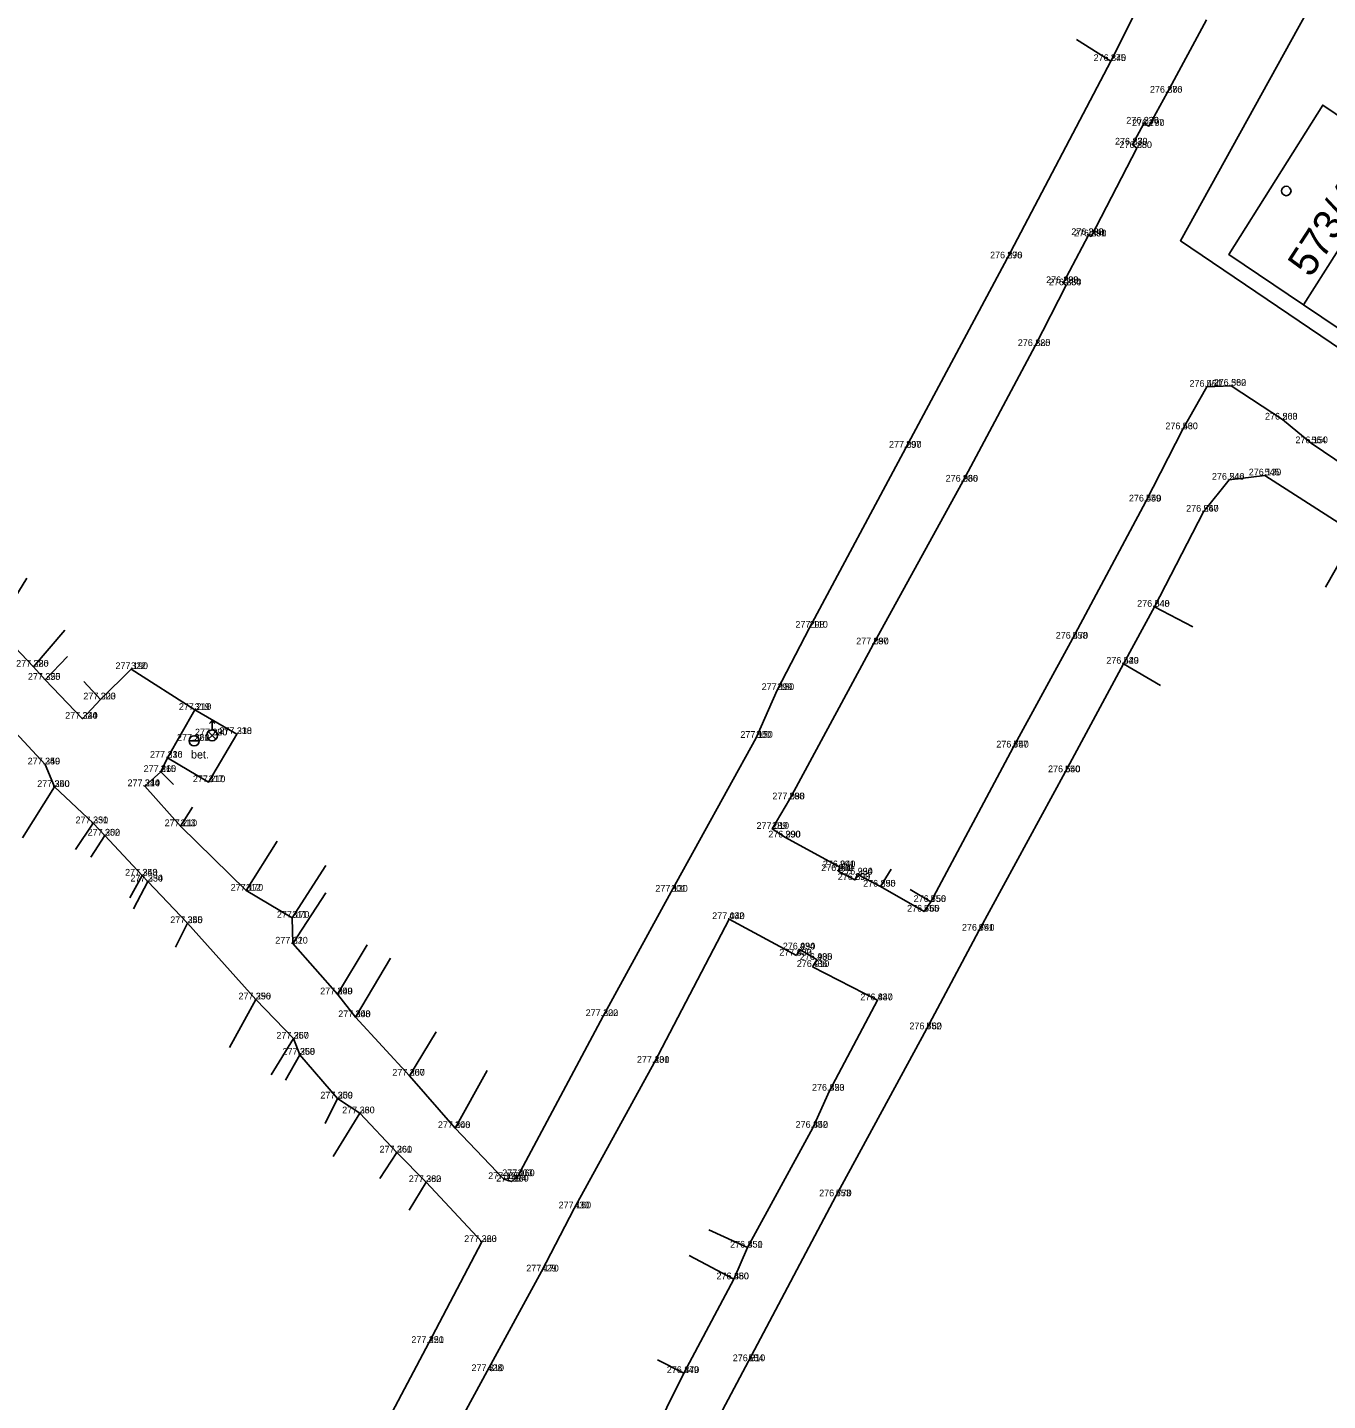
# Model space of a CAD drawing. Extents: x -776701 to -776081, y -974398 to -973771.
# Drawn here: x -776485.8 to -776437.5, y -974052.6 to -974001.5 of the extents above; entities that cross this region are included whole.
import ezdxf

# ---------------------------------------------------------------- set-up
doc = ezdxf.new("R2010")
doc.units = 0
for name, color, linetype in [('1 Body-bod', 7, 'Continuous'), ('10 Silnice-chodniky', 7, 'Continuous'), ('11 Rozhrani-nezpev zpev schody', 7, 'Continuous'), ('2 Body-cislo', 7, 'Continuous'), ('3 Body-vyska', 7, 'Continuous'), ('35 Studna', 7, 'Continuous'), ('40 Popis-povrch', 7, 'Continuous'), ('58 Mobiliar', 7, 'Continuous'), ('7 Ploty', 7, 'Continuous'), ('Hranice parcel', 7, 'Continuous'), ('Parcelní čísla', 7, 'Continuous'), ('Značky budov', 7, 'Continuous')]:
    doc.layers.add(name, color=color, linetype=linetype)

msp = doc.modelspace()

# ---------------------------------------------------------------- linework, layer by layer
at = {"layer": '1 Body-bod'}
for p, q in [((-776445.52, -974002.73), (-776445.52, -974002.73)), ((-776443.42, -974003.91), (-776443.42, -974003.91)), ((-776444.29, -974005.06), (-776444.29, -974005.06)), ((-776444.1, -974005.15), (-776444.1, -974005.15)), ((-776444.71, -974005.84), (-776444.71, -974005.84)), ((-776444.55, -974005.97), (-776444.55, -974005.97)), ((-776446.35, -974009.21), (-776446.35, -974009.21)), ((-776446.25, -974009.26), (-776446.25, -974009.26)), ((-776449.38, -974010.08), (-776449.38, -974010.08)), ((-776447.29, -974011), (-776447.29, -974011)), ((-776447.18, -974011.08), (-776447.18, -974011.08)), ((-776448.33, -974013.34), (-776448.33, -974013.34)), ((-776441.95, -974014.86), (-776441.95, -974014.86)), ((-776441.04, -974014.82), (-776441.04, -974014.82)), ((-776439.13, -974016.08), (-776439.13, -974016.08)), ((-776442.84, -974016.44), (-776442.84, -974016.44)), ((-776453.14, -974017.13), (-776453.14, -974017.13)), ((-776438.06, -974016.96), (-776438.06, -974016.96)), ((-776441.11, -974018.32), (-776441.11, -974018.32)), ((-776439.79, -974018.16), (-776439.79, -974018.16)), ((-776451.03, -974018.39), (-776451.03, -974018.39)), ((-776444.21, -974019.13), (-776444.21, -974019.13)), ((-776442.07, -974019.51), (-776442.07, -974019.51)), ((-776443.89, -974023.05), (-776443.89, -974023.05)), ((-776456.73, -974023.83), (-776456.73, -974023.83)), ((-776454.36, -974024.45), (-776454.36, -974024.45)), ((-776446.94, -974024.24), (-776446.94, -974024.24)), ((-776485.61, -974025.28), (-776485.61, -974025.28)), ((-776481.98, -974025.37), (-776481.98, -974025.37)), ((-776445.04, -974025.17), (-776445.04, -974025.17)), ((-776485.17, -974025.77), (-776485.17, -974025.77)), ((-776483.11, -974026.5), (-776483.11, -974026.5)), ((-776457.93, -974026.15), (-776457.93, -974026.15)), ((-776479.61, -974026.89), (-776479.61, -974026.89)), ((-776483.79, -974027.22), (-776483.79, -974027.22)), ((-776479.63, -974028.04), (-776479.63, -974028.04)), ((-776478.96, -974027.84), (-776478.96, -974027.84)), ((-776478.04, -974027.79), (-776478.04, -974027.79)), ((-776458.72, -974027.93), (-776458.72, -974027.93)), ((-776449.15, -974028.29), (-776449.15, -974028.29)), ((-776485.18, -974028.92), (-776485.18, -974028.92)), ((-776480.62, -974028.67), (-776480.62, -974028.67)), ((-776480.87, -974029.2), (-776480.87, -974029.2)), ((-776479.09, -974029.58), (-776479.09, -974029.58)), ((-776447.22, -974029.21), (-776447.22, -974029.21)), ((-776484.83, -974029.76), (-776484.83, -974029.76)), ((-776481.47, -974029.73), (-776481.47, -974029.73)), ((-776457.48, -974030.22), (-776457.48, -974030.22)), ((-776483.39, -974031.11), (-776483.39, -974031.11)), ((-776482.95, -974031.57), (-776482.95, -974031.57)), ((-776480.14, -974031.22), (-776480.14, -974031.22)), ((-776458.12, -974031.32), (-776458.12, -974031.32)), ((-776457.63, -974031.64), (-776457.63, -974031.64)), ((-776481.56, -974033.06), (-776481.56, -974033.06)), ((-776455.66, -974032.89), (-776455.66, -974032.89)), ((-776455.6, -974032.75), (-776455.6, -974032.75)), ((-776454.94, -974033.02), (-776454.94, -974033.02)), ((-776481.35, -974033.28), (-776481.35, -974033.28)), ((-776477.7, -974033.62), (-776477.7, -974033.62)), ((-776461.88, -974033.66), (-776461.88, -974033.66)), ((-776455.04, -974033.22), (-776455.04, -974033.22)), ((-776454.09, -974033.47), (-776454.09, -974033.47)), ((-776452.22, -974034.04), (-776452.22, -974034.04)), ((-776475.98, -974034.63), (-776475.98, -974034.63)), ((-776459.72, -974034.68), (-776459.72, -974034.68)), ((-776452.47, -974034.4), (-776452.47, -974034.4)), ((-776479.88, -974034.83), (-776479.88, -974034.83)), ((-776450.43, -974035.11), (-776450.43, -974035.11)), ((-776475.96, -974035.59), (-776475.96, -974035.59)), ((-776457.21, -974036.04), (-776457.21, -974036.04)), ((-776457.09, -974035.81), (-776457.09, -974035.81)), ((-776456.45, -974036.2), (-776456.45, -974036.2)), ((-776456.62, -974036.46), (-776456.62, -974036.46)), ((-776477.34, -974037.67), (-776477.34, -974037.67)), ((-776474.3, -974037.48), (-776474.3, -974037.48)), ((-776454.2, -974037.7), (-776454.2, -974037.7)), ((-776473.63, -974038.33), (-776473.63, -974038.33)), ((-776464.41, -974038.29), (-776464.41, -974038.29)), ((-776452.38, -974038.78), (-776452.38, -974038.78)), ((-776475.93, -974039.13), (-776475.93, -974039.13)), ((-776475.7, -974039.73), (-776475.7, -974039.73)), ((-776462.51, -974040.03), (-776462.51, -974040.03)), ((-776471.61, -974040.51), (-776471.61, -974040.51)), ((-776455.99, -974041.07), (-776455.99, -974041.07)), ((-776474.29, -974041.36), (-776474.29, -974041.36)), ((-776473.47, -974041.91), (-776473.47, -974041.91)), ((-776469.92, -974042.46), (-776469.92, -974042.46)), ((-776456.61, -974042.45), (-776456.61, -974042.45)), ((-776472.09, -974043.37), (-776472.09, -974043.37)), ((-776468.11, -974044.36), (-776468.11, -974044.36)), ((-776467.59, -974044.25), (-776467.59, -974044.25)), ((-776471, -974044.47), (-776471, -974044.47)), ((-776467.81, -974044.45), (-776467.81, -974044.45)), ((-776455.75, -974045), (-776455.75, -974045)), ((-776465.49, -974045.45), (-776465.49, -974045.45)), ((-776468.93, -974046.7), (-776468.93, -974046.7)), ((-776459.04, -974046.91), (-776459.04, -974046.91)), ((-776466.7, -974047.8), (-776466.7, -974047.8)), ((-776459.55, -974048.09), (-776459.55, -974048.09)), ((-776470.9, -974050.46), (-776470.9, -974050.46)), ((-776468.72, -974051.51), (-776468.72, -974051.51)), ((-776461.41, -974051.58), (-776461.41, -974051.58)), ((-776459, -974051.14), (-776459, -974051.14))]:
    msp.add_line(p, q, dxfattribs=at)
at = {"layer": '10 Silnice-chodniky'}
msp.add_lwpolyline([(-776480.62, -974028.67), (-776479.09, -974029.58), (-776478.04, -974027.79), (-776479.61, -974026.89), (-776480.62, -974028.67)], dxfattribs=at)
at = {"layer": '11 Rozhrani-nezpev zpev schody'}
for points in [[(-776446.44, -973998.55), (-776444.39, -974000.49), (-776445.52, -974002.73), (-776446.8, -974001.933)], [(-776497.67, -974019.42), (-776496.18, -974016.86), (-776494.82, -974020.13), (-776494.36, -974019.14), (-776490.24, -974023.48), (-776485.18, -974028.92), (-776484.83, -974029.76)], [(-776443.89, -974023.05), (-776445.04, -974025.17)], [(-776485.17, -974025.77), (-776485.61, -974025.28)], [(-776479.61, -974026.89), (-776481.98, -974025.37), (-776483.11, -974026.5)], [(-776480.87, -974029.2), (-776480.62, -974028.67)], [(-776457.48, -974030.22), (-776458.12, -974031.32), (-776457.63, -974031.64)], [(-776483.39, -974031.11), (-776482.95, -974031.57)], [(-776477.7, -974033.62), (-776480.14, -974031.22)], [(-776481.56, -974033.06), (-776481.35, -974033.28)], [(-776454.09, -974033.47), (-776452.47, -974034.4), (-776452.22, -974034.04)], [(-776475.96, -974035.59), (-776475.98, -974034.63)], [(-776479.88, -974034.83), (-776477.34, -974037.67)], [(-776473.63, -974038.33), (-776474.3, -974037.48)], [(-776475.93, -974039.13), (-776475.7, -974039.73)], [(-776469.92, -974042.46), (-776471.61, -974040.51)], [(-776474.29, -974041.36), (-776473.47, -974041.91)], [(-776472.09, -974043.37), (-776471, -974044.47)], [(-776459.55, -974048.09), (-776459.04, -974046.91)], [(-776463.32, -974055.44), (-776461.41, -974051.58)]]:
    msp.add_lwpolyline(points, dxfattribs=at)
at = {"layer": '35 Studna'}
msp.add_line((-776479.818, -974028.04), (-776479.443, -974028.04), dxfattribs=at)
msp.add_circle((-776479.63, -974028.04), 0.188, dxfattribs=at)
at = {"layer": '58 Mobiliar'}
for p, q in [((-776478.96, -974027.29), (-776479.06, -974027.39)), ((-776478.96, -974027.639), (-776478.96, -974027.29)), ((-776478.96, -974027.29), (-776478.86, -974027.39)), ((-776478.96, -974027.84), (-776479.103, -974027.698)), ((-776478.96, -974027.84), (-776479.103, -974027.983)), ((-776478.96, -974027.84), (-776478.818, -974027.698)), ((-776478.96, -974027.84), (-776478.96, -974027.84)), ((-776478.96, -974027.84), (-776478.818, -974027.983))]:
    msp.add_line(p, q, dxfattribs=at)
msp.add_circle((-776478.96, -974027.84), 0.202, dxfattribs=at)
at = {"layer": '7 Ploty'}
for points in [[(-776441.96, -974001.2), (-776443.42, -974003.91), (-776444.1, -974005.15), (-776444.29, -974005.06), (-776444.71, -974005.84), (-776444.55, -974005.97), (-776446.25, -974009.26), (-776446.35, -974009.21), (-776447.29, -974011), (-776447.18, -974011.08), (-776448.33, -974013.34), (-776451.03, -974018.39), (-776454.36, -974024.45), (-776457.48, -974030.22)], [(-776445.52, -974002.73), (-776449.38, -974010.08), (-776453.14, -974017.13), (-776456.73, -974023.83), (-776457.93, -974026.15), (-776458.72, -974027.93), (-776461.88, -974033.66), (-776464.41, -974038.29), (-776467.59, -974044.25), (-776467.81, -974044.45), (-776468.11, -974044.36), (-776469.92, -974042.46), (-776468.722, -974040.322)], [(-776452.983, -974033.572), (-776452.22, -974034.04), (-776449.15, -974028.29), (-776446.94, -974024.24), (-776444.21, -974019.13), (-776442.84, -974016.44), (-776441.95, -974014.86), (-776441.04, -974014.82), (-776439.13, -974016.08), (-776438.06, -974016.96), (-776434.96, -974019.05), (-776432.26, -974020.83), (-776429.08, -974022.97), (-776423.6, -974026.6), (-776419.16, -974029.66), (-776418.688, -974029.087), (-776417.908, -974028.081)], [(-776437.527, -974022.326), (-776436.4, -974020.33), (-776439.79, -974018.16), (-776441.11, -974018.32), (-776442.07, -974019.51), (-776443.89, -974023.05), (-776442.463, -974023.801)], [(-776484.446, -974023.915), (-776485.61, -974025.28), (-776487, -974023.84), (-776485.861, -974021.99)], [(-776483.736, -974025.833), (-776483.11, -974026.5), (-776483.79, -974027.22), (-776485.17, -974025.77), (-776484.339, -974024.898)], [(-776443.675, -974025.979), (-776445.04, -974025.17), (-776447.22, -974029.21), (-776450.43, -974035.11), (-776452.38, -974038.78), (-776455.75, -974045), (-776459, -974051.14)], [(-776479.694, -974030.506), (-776480.14, -974031.22), (-776481.47, -974029.73), (-776480.87, -974029.2), (-776480.394, -974029.667)], [(-776486.016, -974031.654), (-776484.83, -974029.76), (-776483.39, -974031.11), (-776484.041, -974032.087)], [(-776483.472, -974032.377), (-776482.95, -974031.57), (-776481.56, -974033.06), (-776482.024, -974033.884)], [(-776457.63, -974031.64), (-776455.6, -974032.75)], [(-776474.724, -974032.682), (-776475.98, -974034.63), (-776477.7, -974033.62), (-776476.535, -974031.776)], [(-776455.6, -974032.75), (-776455.66, -974032.89), (-776455.04, -974033.22), (-776454.94, -974033.02)], [(-776454.94, -974033.02), (-776454.09, -974033.47), (-776453.689, -974032.816)], [(-776481.885, -974034.294), (-776481.35, -974033.28), (-776479.88, -974034.83), (-776480.322, -974035.723)], [(-776473.187, -974035.631), (-776474.3, -974037.48), (-776475.96, -974035.59), (-776474.724, -974033.697)], [(-776473.899, -974063.281), (-776474.85, -974062.94), (-776471.99, -974057.46), (-776470.6, -974054.83), (-776470.52, -974054.83), (-776468.72, -974051.51), (-776466.7, -974047.8), (-776465.49, -974045.45), (-776462.51, -974040.03), (-776459.72, -974034.68), (-776457.21, -974036.04)], [(-776470.623, -974038.873), (-776471.61, -974040.51), (-776473.63, -974038.33), (-776472.326, -974036.136)], [(-776457.21, -974036.04), (-776457.09, -974035.81), (-776456.45, -974036.2), (-776456.62, -974036.46)], [(-776456.62, -974036.46), (-776454.2, -974037.7), (-776455.99, -974041.07)], [(-776478.309, -974039.463), (-776477.34, -974037.67), (-776475.93, -974039.13), (-776476.769, -974040.478)], [(-776476.226, -974040.677), (-776475.7, -974039.73), (-776474.29, -974041.36), (-776474.754, -974042.29)], [(-776460.474, -974046.251), (-776459.04, -974046.91), (-776456.61, -974042.45), (-776455.99, -974041.07)], [(-776474.455, -974043.515), (-776473.47, -974041.91), (-776472.09, -974043.37), (-776472.716, -974044.343)], [(-776471.629, -974045.519), (-776471, -974044.47), (-776468.93, -974046.7), (-776470.9, -974050.46)], [(-776462.39, -974051.086), (-776461.41, -974051.58), (-776459.55, -974048.09), (-776461.215, -974047.204)], [(-776489.299, -974079.171), (-776486.95, -974080.48), (-776484.57, -974076.08), (-776478.73, -974065.29), (-776475.65, -974059.41), (-776474.97, -974058.38), (-776473.85, -974056.04), (-776470.9, -974050.46)], [(-776461.58, -974056), (-776459, -974051.14)]]:
    msp.add_lwpolyline(points, dxfattribs=at)
at = {"layer": 'Hranice parcel'}
for q in [(-776434.84, -974006.26), (-776435.76, -974013.56)]:
    msp.add_line((-776438.35, -974011.81), q, dxfattribs=at)
for points in [[(-776437.4, -973999.42), (-776442.93, -974009.42), (-776352.22, -974070.86)], [(-776434.84, -974006.26), (-776437.63, -974004.37), (-776441.13, -974009.93), (-776438.35, -974011.81)]]:
    msp.add_lwpolyline(points, dxfattribs=at)
at = {"layer": 'Značky budov'}
msp.add_circle((-776438.987, -974007.569), 0.175, dxfattribs=at)

# ---------------------------------------------------------------- texts
at = {"layer": '2 Body-cislo'}
for s, p in [('275', (-776445.52, -974002.73)), ('276', (-776443.42, -974003.91)), ('278', (-776444.29, -974005.06)), ('277', (-776444.1, -974005.15)), ('279', (-776444.71, -974005.84)), ('280', (-776444.55, -974005.97)), ('282', (-776446.35, -974009.21)), ('281', (-776446.25, -974009.26)), ('296', (-776449.38, -974010.08)), ('283', (-776447.29, -974011)), ('284', (-776447.18, -974011.08)), ('285', (-776448.33, -974013.34)), ('561', (-776441.95, -974014.86)), ('562', (-776441.04, -974014.82)), ('560', (-776442.84, -974016.44)), ('563', (-776439.13, -974016.08)), ('564', (-776438.06, -974016.96)), ('297', (-776453.14, -974017.13)), ('286', (-776451.03, -974018.39)), ('546', (-776441.11, -974018.32)), ('545', (-776439.79, -974018.16)), ('559', (-776444.21, -974019.13)), ('547', (-776442.07, -974019.51)), ('548', (-776443.89, -974023.05)), ('298', (-776456.73, -974023.83)), ('287', (-776454.36, -974024.45)), ('558', (-776446.94, -974024.24)), ('549', (-776445.04, -974025.17)), ('326', (-776485.61, -974025.28)), ('322', (-776481.98, -974025.37)), ('325', (-776485.17, -974025.77)), ('299', (-776457.93, -974026.15)), ('323', (-776483.11, -974026.5)), ('324', (-776483.79, -974027.22)), ('319', (-776479.61, -974026.89)), ('318', (-776478.04, -974027.79)), ('321', (-776479.63, -974028.04)), ('320', (-776478.96, -974027.84)), ('300', (-776458.72, -974027.93)), ('557', (-776449.15, -974028.29)), ('316', (-776480.62, -974028.67)), ('349', (-776485.18, -974028.92)), ('315', (-776480.87, -974029.2)), ('550', (-776447.22, -974029.21)), ('350', (-776484.83, -974029.76)), ('314', (-776481.47, -974029.73)), ('317', (-776479.09, -974029.58)), ('288', (-776457.48, -974030.22)), ('351', (-776483.39, -974031.11)), ('313', (-776480.14, -974031.22)), ('289', (-776458.12, -974031.32)), ('352', (-776482.95, -974031.57)), ('290', (-776457.63, -974031.64)), ('292', (-776455.66, -974032.89)), ('291', (-776455.6, -974032.75)), ('353', (-776481.56, -974033.06)), ('354', (-776481.35, -974033.28)), ('293', (-776455.04, -974033.22)), ('294', (-776454.94, -974033.02)), ('312', (-776477.7, -974033.62)), ('301', (-776461.88, -974033.66)), ('295', (-776454.09, -974033.47)), ('555', (-776452.47, -974034.4)), ('556', (-776452.22, -974034.04)), ('355', (-776479.88, -974034.83)), ('311', (-776475.98, -974034.63)), ('432', (-776459.72, -974034.68)), ('551', (-776450.43, -974035.11)), ('310', (-776475.96, -974035.59)), ('434', (-776457.09, -974035.81)), ('433', (-776457.21, -974036.04)), ('436', (-776456.62, -974036.46)), ('435', (-776456.45, -974036.2)), ('309', (-776474.3, -974037.48)), ('356', (-776477.34, -974037.67)), ('437', (-776454.2, -974037.7)), ('308', (-776473.63, -974038.33)), ('302', (-776464.41, -974038.29)), ('552', (-776452.38, -974038.78)), ('357', (-776475.93, -974039.13)), ('358', (-776475.7, -974039.73)), ('431', (-776462.51, -974040.03)), ('307', (-776471.61, -974040.51)), ('453', (-776455.99, -974041.07)), ('359', (-776474.29, -974041.36)), ('360', (-776473.47, -974041.91)), ('306', (-776469.92, -974042.46)), ('452', (-776456.61, -974042.45)), ('361', (-776472.09, -974043.37)), ('362', (-776471, -974044.47)), ('305', (-776468.11, -974044.36)), ('304', (-776467.81, -974044.45)), ('303', (-776467.59, -974044.25)), ('553', (-776455.75, -974045)), ('430', (-776465.49, -974045.45)), ('363', (-776468.93, -974046.7)), ('451', (-776459.04, -974046.91)), ('429', (-776466.7, -974047.8)), ('450', (-776459.55, -974048.09)), ('421', (-776470.9, -974050.46)), ('554', (-776459, -974051.14)), ('428', (-776468.72, -974051.51)), ('449', (-776461.41, -974051.58))]:
    msp.add_text(s, height=0.25, dxfattribs=at).set_placement(p)
at = {"layer": '3 Body-vyska'}
for s, p in [('276.840', (-776446.158, -974002.73)), ('276.880', (-776444.062, -974003.91)), ('276.830', (-776444.941, -974005.06)), ('276.790', (-776444.728, -974005.15)), ('276.830', (-776445.361, -974005.84)), ('276.850', (-776445.195, -974005.97)), ('276.890', (-776446.988, -974009.21)), ('276.890', (-776446.888, -974009.26)), ('276.870', (-776450.012, -974010.08)), ('276.890', (-776447.928, -974011)), ('276.880', (-776447.822, -974011.08)), ('276.820', (-776448.979, -974013.34)), ('276.450', (-776442.591, -974014.86)), ('276.380', (-776441.691, -974014.82)), ('276.430', (-776443.487, -974016.44)), ('276.200', (-776439.779, -974016.08)), ('276.150', (-776438.649, -974016.96)), ('277.090', (-776453.772, -974017.13)), ('276.960', (-776451.664, -974018.39)), ('276.240', (-776441.755, -974018.32)), ('276.130', (-776440.385, -974018.16)), ('276.440', (-776444.844, -974019.13)), ('276.260', (-776442.715, -974019.51)), ('276.340', (-776444.537, -974023.05)), ('277.110', (-776457.256, -974023.83)), ('277.090', (-776454.992, -974024.45)), ('276.470', (-776447.568, -974024.24)), ('276.420', (-776445.685, -974025.17)), ('277.280', (-776486.253, -974025.28)), ('277.190', (-776482.557, -974025.37)), ('277.250', (-776485.816, -974025.77)), ('277.180', (-776458.511, -974026.15)), ('277.200', (-776483.753, -974026.5)), ('277.240', (-776484.429, -974027.22)), ('277.210', (-776480.198, -974026.89)), ('277.230', (-776478.692, -974027.79)), ('277.260', (-776480.269, -974028.04)), ('277.290', (-776479.599, -974027.84)), ('277.150', (-776459.304, -974027.93)), ('276.740', (-776449.778, -974028.29)), ('277.230', (-776481.272, -974028.67)), ('277.250', (-776485.826, -974028.92)), ('277.260', (-776481.509, -974029.2)), ('276.640', (-776447.854, -974029.21)), ('277.240', (-776485.469, -974029.76)), ('277.240', (-776482.109, -974029.73)), ('277.210', (-776479.678, -974029.58)), ('277.090', (-776458.112, -974030.22)), ('277.230', (-776484.042, -974031.11)), ('277.210', (-776480.728, -974031.22)), ('277.010', (-776458.701, -974031.32)), ('277.200', (-776483.593, -974031.57)), ('276.990', (-776458.264, -974031.64)), ('276.940', (-776456.294, -974032.89)), ('276.940', (-776456.234, -974032.75)), ('277.240', (-776482.199, -974033.06)), ('277.230', (-776482.002, -974033.28)), ('276.890', (-776455.678, -974033.22)), ('276.930', (-776455.587, -974033.02)), ('277.170', (-776478.271, -974033.62)), ('277.130', (-776462.469, -974033.66)), ('276.850', (-776454.735, -974033.47)), ('276.760', (-776453.098, -974034.4)), ('276.750', (-776452.855, -974034.04)), ('277.240', (-776480.519, -974034.83)), ('277.170', (-776476.551, -974034.63)), ('277.040', (-776460.352, -974034.68)), ('276.740', (-776451.058, -974035.11)), ('277.220', (-776476.61, -974035.59)), ('276.990', (-776457.724, -974035.81)), ('277.030', (-776457.855, -974036.04)), ('276.910', (-776457.203, -974036.46)), ('276.900', (-776457.088, -974036.2)), ('277.240', (-776474.939, -974037.48)), ('277.290', (-776477.979, -974037.67)), ('276.840', (-776454.838, -974037.7)), ('277.240', (-776474.269, -974038.33)), ('277.220', (-776465.06, -974038.29)), ('276.780', (-776453.012, -974038.78)), ('277.260', (-776476.569, -974039.13)), ('277.260', (-776476.339, -974039.73)), ('277.200', (-776463.153, -974040.03)), ('277.250', (-776472.256, -974040.51)), ('276.820', (-776456.639, -974041.07)), ('277.200', (-776474.933, -974041.36)), ('277.230', (-776474.122, -974041.91)), ('277.240', (-776470.559, -974042.46)), ('276.840', (-776457.248, -974042.45)), ('277.260', (-776472.729, -974043.37)), ('277.280', (-776471.643, -974044.47)), ('277.190', (-776468.687, -974044.36)), ('277.180', (-776468.391, -974044.45)), ('277.160', (-776468.167, -974044.25)), ('276.770', (-776456.372, -974045)), ('277.160', (-776466.067, -974045.45)), ('277.220', (-776469.58, -974046.7)), ('276.850', (-776459.685, -974046.91)), ('277.170', (-776467.271, -974047.8)), ('276.880', (-776460.192, -974048.09)), ('277.250', (-776471.546, -974050.46)), ('276.810', (-776459.587, -974051.14)), ('277.310', (-776469.309, -974051.51)), ('276.870', (-776462.042, -974051.58))]:
    msp.add_text(s, height=0.25, dxfattribs=at).set_placement(p)
at = {"layer": '40 Popis-povrch'}
msp.add_text('bet.', height=0.3, dxfattribs=at).set_placement((-776479.747, -974028.699))
at = {"layer": 'Parcelní čísla'}
msp.add_text('573/43', height=1.1, rotation=57, dxfattribs=at).set_placement((-776438.078, -974010.829))

doc.saveas('drawing.dxf')
